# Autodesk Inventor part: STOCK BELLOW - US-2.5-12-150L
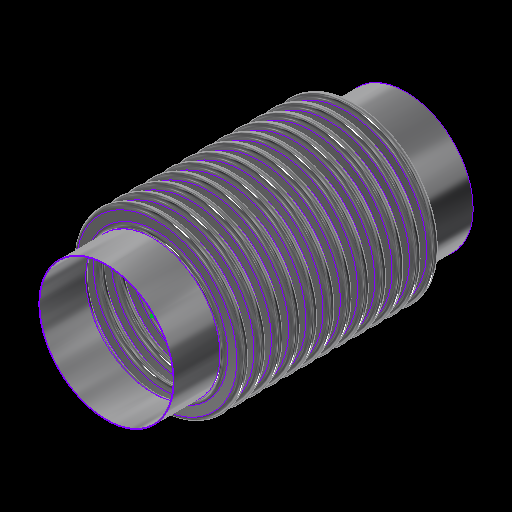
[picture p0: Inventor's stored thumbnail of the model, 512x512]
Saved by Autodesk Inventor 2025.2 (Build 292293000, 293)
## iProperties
Category: 26 GA (0.018 THICK)
RuleStatus: InUse
Created: 2024-01
Part Number: STOCK BELLOW - US-2.5-12-150L
Project: =STOCK BELLOWS: <Stock Number><SFILL>
Material: ASTM A240-304
Description: =STOCK BELLOWS: <Stock Number>, <SID_> I.D., <SOD_> O.D., <SPLY_> PLY, <Category>, <SNET_CONS> CONS.<PITCH_><STANGENT_> TANGENT<SFILL>
Document SubType Name: Sheet Metal
Designer: GS
Stock Number: U.S-2.5-12-85L
Surface Area: 1812.97 cm^2
Volume: 41.2985 cm^3
Sheet Metal Rule: Default
Appearance: STAINLESS STEEL
Mass: 332.754 g
Density: 8.05729 g/cm^3
THK: 0.036
ID: 3.500
OD: 4.250
CONS_: 2
PITCH: 0.500
TANGENT: 0.500
BELLOWS_UPSET: 0.000
d79: 1.000
d82: 1.000
d83: 26.000
d84: 24.000
d174: 8
d214: 8
STHK_: 0.018
SID_: 2.900
SOD_: 3.700
SPITCH_: 0.375
STANGENT__: 1.000
SBELLOWS_UPSET_: 0.000
SDIFF_TAN: 1.000
d252: 2
d275: 2
d287: 0.050
d289: 0.500
d290: 0.000
SOD_NECK: 2 15/16
PLY: 1
PSET: 4.178
PBAR: 1.035
COUNTER: 1.500
NET_TUBE: 3.071
CONS: 2
S_CONS: 0
NET_CONS: 2
ID_M: 88.90 mm
OD_M: 107.95 mm
THK_M: 0.91 mm
ID_U: 3.500 in
OD_U: 4.250 in
THK_U: 0.036 in
TANGENT2: 0.500
TAN_TO_TAN: 1.000 in
d80: 2.571
d81: 10
SID: 2.375
SCONS_: 12
SPITCH: 0.250
STANGENT_: 1.000
SBELLOWS_UPSET: 0.000
SNET_CONS: 12
SS_CONS: 0
SCONS: 8
d190: 8
d191: 1
d192: 1
d193: 8
d194: 0
SIZE: 2.50
PRESSURE: 85
d230: 8
STANGENT: 4.000
SPLY_: 1
d233: 8
d234: 0
d263: 2
d265: 1
d268: 2
d269: 0
d286: 2
d288: 1
d291: 2
d292: 0
SREROLL: 0.750
BLETP: 1.000 ul
PRES_Copy: 85
MATTABLE: 20 GA (0.036 THICK)
PART_NUMBER: U.S-2.5-12-85L
PITCH_: =, <SPITCH_> PITCH,
CFILL: .
SFILL: .
MESH: ,
COMP: 1.12
EXT: 0.56
LAT: 0.50
ANG: 573
ASR: 386
LSR: 312
ANSR: 14
PRES: 85
COMPM: 11.2
EXTM: 5.6
LATM: 5.00
ASRM: 67.600
PRESM: 5.860
LSRM: 54.641
ANSRM: 2.452
TEMPMIN: 20
TEMPMAX: 800
TEMPMINM: -7
TEMPMAXM: 427
WEIGHTM: 0.439
WEIGHT: 0.968
Author: GS
Keywords: 20 GA (0.036 THICK)
Comments: =STOCK BELLOW - <STOCK NUMBER>
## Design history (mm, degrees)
sketch "Sketch2"
  geometry: L1 (0, -177.245)-(0, 562.856) reference; L2 (45.364, 0)-(44.45, 0); L3 (48.082, -2.718)-(50.343, -2.718); L4 (48.082, -3.632)-(50.343, -3.632); L5 (50.343, -9.982)-(48.082, -9.982); L6 (50.343, -9.068)-(48.082, -9.068); L7 (45.364, -12.7)-(44.45, -12.7); L8 (48.082, 0)-(48.082, -12.7); L9 (50.343, -6.35)-(53.975, -6.35); L10 (44.45, 0)-(44.45, -12.7); L11 (20.376, 102.841)-(20.376, 101.926); L12 (58.262, 457.127)-(58.262, 349.177); L13 (58.262, 444.427)-(58.262, 336.477); L14 (93.133, -58.817)-(93.133, -71.517); L15 (118.746, -66.401)-(118.746, -66.401); L16 (50.343, -9.068)-(50.343, -9.982); L17 (48.082, -9.068)-(48.082, -9.982); L18 (48.082, -9.525)-(50.343, -9.525); L19 (53.975, 0)-(53.975, -12.7); L20 (-50.343, -9.068)-(-50.343, -9.982); L21 (-50.343, -2.718)-(-48.082, -2.718); L22 (-50.343, -3.632)-(-48.082, -3.632); L23 (-48.082, -9.068)-(-50.343, -9.068); L24 (-50.343, -9.525)-(-48.082, -9.525); L25 (-48.082, -9.982)-(-50.343, -9.982); L26 (-48.082, -9.068)-(-48.082, -9.982); L27 (-44.45, 0.653)-(-44.45, -12.047); L28 (-48.082, -6.35)-(-44.45, -6.35); L29 (-50.343, 0.653)-(-50.343, -12.7); L30 (-53.061, 0)-(-53.975, 0); L31 (-53.975, 0)-(-53.975, -12.7); L32 (-53.061, -12.7)-(-53.975, -12.7); A1 r 2.718 centre (48.082, 0) between (45.364, 0) and (48.082, -2.718); A2 r 3.632 centre (48.082, 0) between (44.45, 0) and (48.082, -3.632); A3 r 3.632 centre (50.343, -6.35) between (50.343, -9.982) and (50.343, -2.718); A4 r 2.718 centre (50.343, -6.35) between (50.343, -9.068) and (50.343, -3.632); A5 r 2.718 centre (48.082, -12.7) between (48.082, -9.982) and (45.364, -12.7); A6 r 3.632 centre (48.082, -12.7) between (48.082, -9.068) and (44.45, -12.7); A7 r 3.175 centre (50.343, -6.35) between (50.343, -9.525) and (53.518, -6.35); A8 r 3.175 centre (48.082, -12.7) between (48.082, -9.525) and (44.907, -12.7); A9 r 2.718 centre (-50.343, -12.7) between (-50.343, -9.982) and (-53.061, -12.7); A10 r 2.718 centre (-48.082, -6.35) between (-48.082, -9.068) and (-48.082, -3.632); A11 r 3.175 centre (-48.082, -6.35) between (-48.082, -9.525) and (-44.907, -6.35); A12 r 3.632 centre (-48.082, -6.35) between (-48.082, -9.982) and (-48.082, -2.718); A13 r 3.175 centre (-50.343, -12.7) between (-50.343, -9.525) and (-53.518, -12.7); A14 r 3.632 centre (-50.343, -12.7) between (-50.343, -9.068) and (-53.975, -12.7); A15 r 2.718 centre (-50.343, 0) between (-53.061, 0) and (-50.343, -2.718); A16 r 3.632 centre (-50.343, 0) between (-53.975, 0) and (-50.343, -3.632); 10 further points
  constraints: 62 end point, 38 point on circle, 20 tangent, 16 centre point, 12 parallel, 9 midpoint, 7 vertical, 6 coincident, 6 concentric, 6 point on line, 4 equal radius, 4 perpendicular, 3 horizontal, 1 collinear, 1 horizontal alignment, 10 other
  dimensions: "THK" = 0.9144 distance of L11.start L11.end; "ID" = 88.9 distance of L11.end point (20.376, 13.026); "OD" = 107.95 distance of L12.start L12.end; "PITCH" = 12.7 distance of L12.start L13.start; "TANGENT" = 12.7 distance of L14.start L14.end; "BELLOWS_UPSET" = 0 distance of L15.start L15.end; "d43" = 88.9 diameter of L10 L1 (= ID); "d44" = 107.95 diameter of L9.end L1 (= OD); "d45" = 0.9144 distance between parallel lines of L5 L6 (computed from THK, PLY); "d46" = 3.6322 radius of A3 (computed from PITCH, THK, PLY); "UPSET_PITCH" = 12.7 distance of L2.end L7.end (derived); "SIDEWALL_ANGLE" = 360 deg dimension on L3 L9 (derived); "CON_GAP" = 5.4356 distance of point (48.082, -9.068) point (48.082, -3.632) (derived); "TAN1" = 4.98728 dimension on A8 (derived); "TAN2" = 4.98728 dimension on A7 (derived); "LEG1" = 2.2606 distance of L18.start L18.end (derived); "d278" = 0.9144 distance between parallel lines of L25 L23 (derived); "d279" = 3.6322 radius of A12 (derived); "d280" = 12.7 distance of L30.end L31.end (derived); "d281" = 360 deg dimension on L21 L28 (derived); "d282" = 5.4356 distance of point (-50.343, -9.068) point (-50.343, -3.632) (derived); "d283" = 4.98728 dimension on A13 (derived); "d284" = 4.98728 dimension on A11 (derived); "d285" = 2.2606 distance of L24.start L24.end (derived); "d293" = 88.9 diameter of L27 L1 (derived); "d294" = 107.95 diameter of L31 L1 (derived)
  node "Sketch Rectangular Pattern1" dims "d31" = 25.4, "ID" = 88.9
  node "Sketch Rectangular Pattern2" dims "d39" = 25.4, "PITCH" = 12.7
revolve "CONS" stored, may be unused: angle "d48" = 90 deg
node "BELLOW MIDPLANE"
pattern_linear "Rectangular Pattern2" dims "d52" = 12.7 (= UPSET_PITCH)
sketch "Sketch5"
  geometry: C1 r 45.364 at (0, 0) reference; C2 r 44.45 at (0, 0) reference
extrude "TANGENT" new body sketch "Sketch5" distance "d53" = 12.7 (= TANGENT); taper "d54" = 0 deg
revolve "SAMETAN" stored, may be unused: angle "d65" = 90 deg
revolve "DIFFTAN" stored, may be unused: angle "d70" = 90 deg
sketch "Sketch9"
  geometry: L1 (53.319, 0)-(-53.319, 0) reference; L2 (0, -17.78)-(0, 17.78) reference; L3 (38.085, 0)-(-38.085, 0); L4 (38.085, -11.906)-(38.085, 11.906); L5 (25.385, -11.906)-(25.385, 11.906); L6 (13.15, 11.906)-(13.15, -11.906); L7 (-25.385, -11.906)-(-25.385, 11.906); L8 (-38.085, -11.906)-(-38.085, 11.906); L9 (37.291, -11.906)-(37.291, 11.906); L10 (38.085, -11.906)-(37.291, -11.906); L11 (38.085, 11.906)-(37.291, 11.906); L12 (13.546, 11.906)-(12.753, 11.906); L13 (12.753, 11.906)-(12.753, -11.906); L14 (12.753, -11.906)-(13.546, -11.906); L15 (13.546, -11.906)-(13.546, 11.906); L16 (-13.546, 11.906)-(-13.546, -11.906); L17 (-13.15, 11.906)-(-13.15, -11.906); L18 (-13.546, -11.906)-(-12.753, -11.906); L19 (-12.753, -11.906)-(-12.753, 11.906); L20 (-12.753, 11.906)-(-13.546, 11.906); L21 (-38.085, -11.906)-(-37.291, -11.906); L22 (-37.291, -11.906)-(-37.291, 11.906); L23 (-37.291, 11.906)-(-38.085, 11.906); L24 (-38.085, 11.906)-(-38.085, -11.906); L25 (38.085, -0.397)-(-38.085, -0.397); L26 (-38.085, -0.397)-(-38.085, 0.397); L27 (-38.085, 0.397)-(38.085, 0.397); L28 (38.085, 0.397)-(38.085, -0.397); L29 (-38.085, 11.906)-(38.085, 11.906); L30 (38.085, 11.906)-(38.085, 12.7); L31 (38.085, 12.7)-(-38.085, 12.7); L32 (-38.085, 12.7)-(-38.085, 11.906); L33 (38.085, -11.906)-(-38.085, -11.906); L34 (-38.085, -11.906)-(-38.085, -12.7); L35 (-38.085, -12.7)-(38.085, -12.7); L36 (38.085, -12.7)-(38.085, -11.906); 30 further points
  constraints: 68 end point, 13 midpoint, 13 parallel, 8 horizontal, 7 perpendicular, 6 equal length, 3 point on line, 2 vertical, 14 other
  dimensions: "d115" = 23.8125 distance of L4.start L4.end (derived); "d116" = 12.7 distance between parallel lines of L4 L5 (derived); "d117" = 12.23516 distance between parallel lines of L5 L6 (derived); "d125" = 38.53427 distance between parallel lines of L7 L6 (derived); "d127" = 12.7 distance between parallel lines of L8 L7 (derived); "d128" = 24.93516 distance between parallel lines of L6 L4 (derived); "d130" = 76.16943 distance between parallel lines of L8 L4 (derived); "RULER_THK" = 0.79375 distance between parallel lines of L4 L9; "d135" = 0.79375 distance of L13.end L14.end (derived); "d138" = 26.29911 distance of L13.end L16.end (derived); "d143" = 0.79375 distance of L22.end L8.end (derived); "d144" = 0.79375 distance between parallel lines of L27 L25 (derived)
extrude "RULER" join sketch "Sketch9" distance "d149" = 0.79375 (derived); taper "d150" = 0 deg
extrude "BARS" join sketch "Sketch9" distance "d151" = 0.79375 (derived); taper "d152" = 0 deg
pattern_linear "Rectangular Pattern4" dims "d155" = 26.29911 (derived)
sketch "Sketch13"
  geometry: L1 (93.149, -52.467)-(93.149, -77.867); L2 (37.287, 0)-(36.83, 0); L3 (37.287, -9.525)-(36.83, -9.525); L4 (44.38, -7.372)-(39.44, -7.372); L5 (44.38, -6.915)-(39.44, -6.915); L6 (44.38, -4.763)-(46.99, -4.763); L7 (39.44, -2.153)-(44.38, -2.153); L8 (39.44, 0)-(39.44, -9.525); L9 (36.83, 0)-(36.83, -9.525); L10 (58.254, -402.451)-(58.254, -496.431); L11 (58.254, -411.976)-(58.254, -505.956); L12 (58.254, -431.026)-(58.254, -525.006); L13 (58.254, -440.551)-(58.254, -534.531); L14 (58.254, -450.076)-(58.254, -544.056); L15 (58.254, -459.601)-(58.254, -553.581); L16 (58.254, -469.126)-(58.254, -563.106); L17 (58.254, -421.501)-(58.254, -515.481); L18 (20.376, 102.383)-(20.376, 101.926); L19 (39.44, -2.61)-(44.38, -2.61); L20 (0, -696.234)-(0, 235.664) reference; L21 (-23.752, 0)-(142.514, 0) reference; A1 r 2.153 centre (39.44, 0) between (37.287, 0) and (39.44, -2.153); A2 r 2.153 centre (39.44, -9.525) between (39.44, -7.372) and (37.287, -9.525); A3 r 2.61 centre (39.44, -9.525) between (39.44, -6.915) and (36.83, -9.525); A4 r 2.153 centre (44.38, -4.763) between (44.38, -6.915) and (44.38, -2.61); A5 r 2.61 centre (44.38, -4.763) between (44.38, -7.372) and (44.38, -2.153); A6 r 2.61 centre (39.44, 0) between (36.83, 0) and (39.44, -2.61); 6 further points; 1 other entity
  constraints: 38 end point, 15 point on circle, 9 tangent, 6 centre point, 6 parallel, 5 vertical alignment, 4 point on line, 4 vertical, 3 coincident, 3 concentric, 2 collinear, 2 equal radius, 1 horizontal, 1 perpendicular, 23 other
  dimensions: "SBELLOWS_UPSET_" = 0 distance of point (118.762, -66.401) point (118.762, -66.401); "STOTAL_THK_BELLOW__" = 0.4572 distance between parallel lines of L4 L5 (derived); "d224" = 2.60985 radius of A5 (derived); "d225" = 9.525 distance of L2.end L3.end (derived); "SSIDEWALL_ANGLE_" = 360 deg dimension on L7 L6 (derived); "SSCON_GAP_" = 4.3053 distance of point (39.44, -6.915) point (39.44, -2.61) (derived); "d235" = 73.66 diameter of L9 L20 (derived); "d236" = 93.98 diameter of L6.end L20 (derived)
  node "Sketch Rectangular Pattern4" dims "d228" = 25.4
  node "Sketch Rectangular Pattern5" dims "d229" = 25.4
revolve "SBELLOW" stored, may be unused: angle "d197" = 90 deg
pattern_linear "Rectangular Pattern5" dims "d204" = 9.525 (derived)
revolve "STANGENT" stored, may be unused: angle "d240" = 90 deg
revolve "SSAMETAN" stored, may be unused: angle "d241" = 90 deg
revolve "SDIFFTAN" stored, may be unused: angle "d246" = 90 deg
revolve "INVCON" stored, may be unused: angle "d295" = 90 deg
pattern_linear "Rectangular Pattern6" dims "d298" = 12.7 (derived)
revolve "INVTANGENT" stored, may be unused: angle "d302" = 90 deg
revolve "INVSAMETAN" stored, may be unused: angle "d307" = 90 deg
revolve "INVDIFFTAN" stored, may be unused: angle "d312" = 90 deg
sketch "ID BELLOW MOUNT CALC"
  geometry: L1 (44.45, 0)-(38.1, 0); L2 (38.1, 0)-(38.1, 12.7); L3 (38.1, 12.7)-(44.45, 12.7); L4 (44.45, 12.7)-(44.45, 0); L5 (36.513, 12.7)-(35.598, 12.7); L6 (35.598, 12.7)-(35.598, 0); L7 (35.598, 0)-(36.513, 0); L8 (36.513, 0)-(36.513, 12.7); L9 (0, -2.54)-(0, 15.24) reference; L10 (-8.89, 0)-(53.34, 0) reference; 1 further point
  constraints: 16 end point, 5 parallel, 2 collinear, 2 horizontal, 2 perpendicular
  dimensions: "d314" = 12.7 distance of L5.end L6.end (derived); "d315" = 0.9144 distance of L5.start L5.end (derived); "IG" = 1.5875 distance between parallel lines of L2 L8; "PIPE_OD" = 88.9 diameter of L4 L9; "PIPE_WALL" = 6.35 distance of L2.end L3.end; "ID_MT_BELLOW" = 71.1962 diameter of L6 L9 (derived)
revolve "CFILL" stored, may be unused: angle "d320" = 90 deg
pattern_linear "Rectangular Pattern7" dims "d323" = 12.7 (derived)
revolve "SFILL" stored, may be unused: angle "d324" = 90 deg
pattern_linear "Rectangular Pattern8" dims "d327" = 9.525 (derived)
node "STOCK BELLOW MIDPLANE"
node "BELLOW"
sketch "Sketch6"
  geometry: L1 (-12.7, 45.364)-(0, 45.364); L2 (0, 45.364)-(0, 44.45); L3 (0, 44.45)-(-12.7, 44.45); L4 (-12.7, 44.45)-(-12.7, 45.364); L5 (10.16, 0)-(-60.96, 0) reference; L6 (-38.1, -89.422)-(-38.1, 153.44) reference; 1 further point
  constraints: 8 end point, 2 parallel, 1 horizontal, 1 perpendicular
  dimensions: "d61" = 12.7 distance of L2.end L3.end (derived); "d62" = 0.9144 distance of L1.end L2.end (derived); "d63" = 88.9 diameter of L3 L5 (derived); "d64" = 25.4 distance between parallel lines of L4 L6 (derived)
sketch "Sketch12"
  geometry: 1 further point
sketch "Sketch14"
  geometry: L1 (-25.4, 37.287)-(0, 37.287); L2 (0, 37.287)-(0, 36.83); L3 (0, 36.83)-(-25.4, 36.83); L4 (-25.4, 36.83)-(-25.4, 37.287); L5 (5.08, 0)-(-30.48, 0) reference; L6 (0, -8.89)-(0, 53.34) reference; 1 further point
  constraints: 8 end point, 2 parallel, 1 collinear, 1 horizontal, 1 perpendicular
  dimensions: "d237" = 0.4572 distance of L3.end L1.start (derived); "d238" = 73.66 diameter of L3 L5 (derived); "d239" = 25.4 distance of L1.start L1.end (derived); "SOD_NECK" = 74.5744 diameter of L1 L5 (derived)
sketch "Sketch15"
  geometry: L1 (-8.89, 0)-(53.34, 0) reference; L2 (36.83, -114.3)-(37.287, -114.3); L3 (37.287, -114.3)-(37.287, -139.7); L4 (37.287, -139.7)-(36.83, -139.7); L5 (36.83, -139.7)-(36.83, -114.3); L6 (0, -170.18)-(0, 43.18) reference; 1 further point
  constraints: 8 end point, 2 parallel, 1 horizontal, 1 perpendicular
  dimensions: "d205" = 25.4 distance of L4.end L2.start (derived); "d206" = 0.4572 distance of L3.end L4.end (derived); "d207" = 73.66 diameter of L5 L6 (derived); "d208" = 114.3 distance between parallel lines of L1 L2 (derived)
node "TANGENT_"
node "SAME_TAN"
sketch "Sketch8"
  geometry: L1 (45.364, -25.4)-(44.45, -25.4); L2 (44.45, -25.4)-(44.45, -38.1); L3 (44.45, -38.1)-(45.364, -38.1); L4 (45.364, -38.1)-(45.364, -25.4); L5 (0, -48.26)-(0, 22.86) reference; L6 (-89.422, 0)-(153.44, 0) reference; 1 further point
  constraints: 8 end point, 2 parallel, 1 horizontal, 1 perpendicular
  dimensions: "d66" = 88.9 diameter of L2 L5 (derived); "TOTAL_THK_BELLOW" = 0.9144 distance of L2.end L3.end (derived); "d68" = 25.4 distance between parallel lines of L1 L6 (derived); "d69" = 12.7 distance of L1.end L2.end (derived)
node "DIFF_TAN"
node "Sketch Rectangular Pattern3" dims "d138" = 26.29911 (derived), "d141" = 25.4
node "SBELLOW_"
node "STANGENT_"
node "SSAME_TAN"
sketch "Sketch16"
  geometry: L1 (37.287, -114.3)-(36.83, -114.3); L2 (36.83, -114.3)-(36.83, -139.7); L3 (36.83, -139.7)-(37.287, -139.7); L4 (37.287, -139.7)-(37.287, -114.3); L5 (0, -170.18)-(0, 43.18) reference; L6 (-8.89, 0)-(53.34, 0) reference; 1 further point
  constraints: 8 end point, 2 parallel, 1 horizontal, 1 perpendicular
  dimensions: "SDIFF_TAN" = 25.4 distance of L3.end L1.start; "d243" = 0.4572 distance of L2.end L3.end (derived); "d244" = 114.3 distance between parallel lines of L1 L6 (derived); "d245" = 73.66 diameter of L2 L5 (derived)
node "SDIFF_TAN"
body "Solid15"
sketch "Sketch17"
  geometry: L1 (53.975, 12.7)-(53.061, 12.7); L2 (53.061, 12.7)-(53.061, 0); L3 (53.061, 0)-(53.975, 0); L4 (53.975, 0)-(53.975, 12.7); L5 (0, -2.54)-(0, 15.24) reference; L6 (-10.795, 0)-(64.77, 0) reference; 2 further points
  constraints: 8 end point, 2 parallel, 1 horizontal, 1 midpoint, 1 perpendicular, 1 point on line
  dimensions: "INVTANGENT" = 12.7 distance of L3.end L1.start (derived); "d300" = 0.9144 distance of L1.start L1.end (derived); "d301" = 107.95 diameter of L4 L5 (derived)
body "Solid16"
sketch "Sketch18"
  geometry: L1 (53.975, -25.4)-(53.061, -25.4); L2 (53.061, -25.4)-(53.061, -38.1); L3 (53.061, -38.1)-(53.975, -38.1); L4 (53.975, -38.1)-(53.975, -25.4); L5 (-10.795, 0)-(64.77, 0) reference; L6 (0, -48.26)-(0, 22.86) reference; 1 further point
  constraints: 8 end point, 2 parallel, 1 horizontal, 1 perpendicular
  dimensions: "d303" = 25.4 distance between parallel lines of L1 L5 (derived); "d304" = 12.7 distance of L3.end L1.start (derived); "d305" = 0.9144 distance of L2.end L3.end (derived); "d306" = 107.95 diameter of L4 L6 (derived)
body "Solid17"
sketch "Sketch19"
  geometry: L1 (53.975, -25.4)-(53.061, -25.4); L2 (53.061, -25.4)-(53.061, -38.1); L3 (53.061, -38.1)-(53.975, -38.1); L4 (53.975, -38.1)-(53.975, -25.4); L5 (0, -48.26)-(0, 22.86) reference; L6 (-10.795, 0)-(64.77, 0) reference; 1 further point
  constraints: 8 end point, 2 parallel, 1 horizontal, 1 perpendicular
  dimensions: "d308" = 12.7 distance of L1.end L2.end (derived); "d309" = 107.95 diameter of L4 L5 (derived); "d310" = 0.9144 distance of L2.end L3.end (derived); "d311" = 25.4 distance between parallel lines of L1 L6 (derived)
body "Solid18"
body "Solid19"
body "Solid20"
other parameters: "BMPL" = -57.15, "PSET" = 106.1212 (computed from OD, THK, PLY) [user parameter], "PBAR" = 26.29911 (= 0.570796 x PITCH + OD - ID) [user parameter; used in 1 equation term], "COUNTER" = 15 [user parameter], "NET_TUBE" = 77.99823 (computed from CONS_, PBAR, TANGENT) [user parameter], "S_CONS" = 0 [user parameter; used in 1 equation term], "ID_M" = 88.9 (= ID) [user parameter], "OD_M" = 107.95 (= OD) [user parameter], "THK_M" = 0.9144 (= THK) [user parameter], "ID_U" = 88.9 (= ID) [user parameter], "OD_U" = 107.95 (= OD) [user parameter], "THK_U" = 0.9144 (= THK) [user parameter], "D_UNITS" = 0 [user parameter], "TANGENT2" = 12.7 [user parameter], "TAN_TO_TAN" = 25.4 [user parameter], "OD_NECK" = 90.7288 [user parameter], "d79" = 25.4, "d80" = 65.29823 [user parameter], "d82" = 25.4, "d83" = 660.4, "d84" = 609.6, "sa_0" = 4, "FRAME_THK" = 0.79375 [user parameter], "CON_FLAT" = 12.23516 [user parameter], "SID" = 60.325 [user parameter], "SPITCH" = 6.35 [user parameter], "STANGENT_" = 25.4 [user parameter], "SBELLOWS_UPSET" = 0 [user parameter], "SS_CONS" = 0 [user parameter], "STAN_TO_TAN_" = 114.3 [user parameter], "d100" = 0.4572 [user parameter], "d191" = 25.4 [user parameter], "d194" = 0 [user parameter], "STANGENT" = 101.6 [user parameter], "d234" = 0 [user parameter], "SUPSET_PITCH_" = 9.525 [user parameter], "d269" = 0 [user parameter], "d287" = 1.27, "d289" = 12.7, "d290" = 0, "d292" = 0 [user parameter], "Thickness" = 3.048 (derived), "KFactor" = 4.4, "BendRadius" = 3.048 (derived), "BendReliefWidth" = 3.048 (derived), "BendReliefDepth" = 1.524 (derived), "CornerReliefSize" = 12.192 (derived), "SeamGap" = 0.00508, "MinimumRemnant" = 6.096 (derived), "TransitionRadius" = 3.048 (derived), "JacobiRadiusSize" = 3.048 (derived), "GapSize" = 3.048 (derived), "SREROLL" = 19.05 [user parameter], "CUR_STK_PITCH" = 9.525 [user parameter], "d328" = -57.15 (derived), "BLETP" = 1 [user parameter], "ASRM" = 676.0018 [user parameter], "PRESM" = 58.60452 [user parameter], "LSRM" = 546.4056 [user parameter], "ANSRM" = 24.5182 [user parameter], "TEMPMIN" = 2664.83333 [user parameter], "TEMPMAX" = 6998.16667 [user parameter], "TEMPMINM" = 2664.83333 [user parameter], "TEMPMAXM" = 6998.16667 [user parameter], "WEIGHT" = 4.39061 [user parameter], "WEIGHTM" = 0.00439 [user parameter]
